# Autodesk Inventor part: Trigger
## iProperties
Created: 2009-03
Part Number: Trigger
Document SubType Name: Modeling
Designer: tangg
Density: 7.85 g/cm^3
Material: Steel
Mass: 29.3702 g
Surface Area: 74.34 cm^2
Volume: 3.74142 cm^3
Author: tangg
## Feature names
1. Extrusion1
2. Shell6
3. Extrusion2
4. Extrusion3
5. Extrusion4
